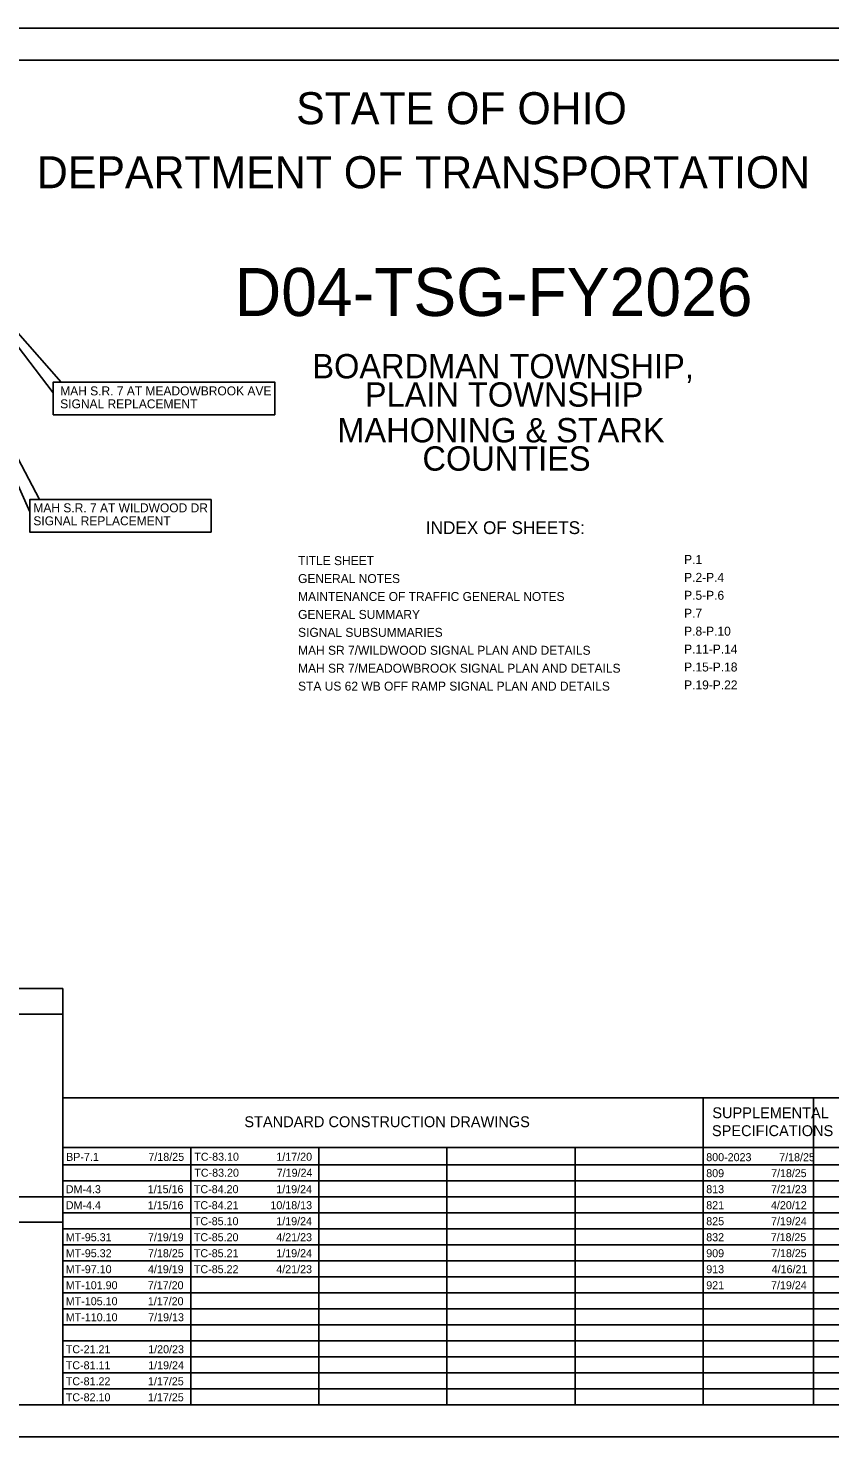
# Model space of a CAD drawing. Extents: x 0 to 29006, y 0 to 889393.
# Drawn here: x 9.61 to 22.13, y 0 to 22 of the extents above; entities that cross this region are included whole.
import ezdxf

# ---------------------------------------------------------------- set-up
doc = ezdxf.new("R2010")
doc.units = 0
for name, color, linetype in [('Default', 7, 'Continuous'), ('SH_Border', 7, 'Continuous'), ('SH_Cut_Line', 7, 'Continuous'), ('SH_Data', 7, 'Continuous'), ('SH_Text', 7, 'Continuous')]:
    doc.layers.add(name, color=color, linetype=linetype)

msp = doc.modelspace()

# ---------------------------------------------------------------- linework, layer by layer
at = {"layer": 'Default'}
for points in [[(10.002, 16.307), (8.244, 18.612), (10.126, 16.474), (10.002, 16.474)], [(9.635, 14.448), (8.269, 17.529), (9.789, 14.637), (9.635, 14.637)], [(10.002, 16.474), (13.461, 16.474), (13.461, 15.962), (10.002, 15.962)], [(9.635, 14.637), (12.467, 14.637), (12.467, 14.131), (9.635, 14.131)]]:
    msp.add_lwpolyline(points, close=True, dxfattribs=at)
at = {"layer": 'SH_Border'}
msp.add_lwpolyline([(1.5, 21.5), (33.5, 21.5), (33.5, 0.5), (1.5, 0.5)], close=True, dxfattribs=at)
at = {"layer": 'SH_Cut_Line'}
msp.add_lwpolyline([(0, 0), (34, 0), (34, 22), (0, 22)], close=True, dxfattribs=at)
at = {"layer": 'SH_Data'}
for p, q in [((7.35, 6.6), (10.15, 6.6)), ((10.15, 5.292), (23.6, 5.292)), ((10.15, 0.5), (10.15, 5.292)), ((20.15, 0.5), (20.15, 5.292)), ((21.875, 0.5), (21.875, 5.292)), ((10.15, 4.521), (23.6, 4.521)), ((12.15, 0.5), (12.15, 4.521)), ((14.15, 0.5), (14.15, 4.521)), ((16.15, 0.5), (16.15, 4.521)), ((18.15, 0.5), (18.15, 4.521)), ((10.15, 4.25), (23.6, 4.25)), ((10.15, 4), (23.6, 4)), ((10.15, 3.75), (23.6, 3.75)), ((7.35, 3.35), (10.15, 3.35)), ((10.15, 3.5), (23.6, 3.5)), ((10.15, 3.25), (23.6, 3.25)), ((10.15, 3), (23.6, 3)), ((10.15, 2.75), (23.6, 2.75)), ((10.15, 2.5), (23.6, 2.5)), ((10.15, 2.25), (23.6, 2.25)), ((10.15, 2), (23.6, 2)), ((10.15, 1.75), (23.6, 1.75)), ((10.15, 1.5), (23.6, 1.5)), ((10.15, 1.25), (23.6, 1.25)), ((10.15, 1), (23.6, 1)), ((10.15, 0.75), (23.6, 0.75))]:
    msp.add_line(p, q, dxfattribs=at)
for points in [[(10.15, 7), (7.35, 7), (7.35, 3.75), (10.15, 3.75)], [(10.15, 3.75), (7.35, 3.75), (7.35, 0.5), (10.15, 0.5)]]:
    msp.add_lwpolyline(points, close=True, dxfattribs=at)

# ---------------------------------------------------------------- texts
at = {"layer": 'Default'}
for s, height, p in [('BP-7.1', 0.125, (10.203, 4.31)), ('7/18/25', 0.125, (11.488, 4.31)), ('TC-83.10', 0.125, (12.205, 4.312)), ('1/17/20', 0.125, (13.486, 4.312)), ('800-2023', 0.125, (20.198, 4.305)), ('7/18/25', 0.125, (21.337, 4.305)), ('TC-83.20', 0.125, (12.205, 4.062)), ('7/19/24', 0.125, (13.492, 4.062)), ('809', 0.125, (20.198, 4.055)), ('7/18/25', 0.1237, (21.213, 4.056)), ('DM-4.3', 0.125, (10.198, 3.805)), ('1/15/16', 0.125, (11.478, 3.805)), ('TC-84.20', 0.125, (12.198, 3.805)), ('1/19/24', 0.125, (13.485, 3.805)), ('813', 0.125, (20.198, 3.805)), ('7/21/23', 0.125, (21.21, 3.805)), ('DM-4.4', 0.125, (10.198, 3.555)), ('1/15/16', 0.125, (11.478, 3.555)), ('TC-84.21', 0.125, (12.198, 3.555)), ('10/18/13', 0.125, (13.393, 3.555)), ('821', 0.125, (20.198, 3.555)), ('4/20/12', 0.125, (21.209, 3.555)), ('TC-85.10', 0.125, (12.198, 3.305)), ('1/19/24', 0.125, (13.485, 3.305)), ('825', 0.125, (20.198, 3.305)), ('7/19/24', 0.125, (21.21, 3.305)), ('MT-95.31', 0.125, (10.198, 3.055)), ('7/19/19', 0.125, (11.481, 3.055)), ('TC-85.20', 0.125, (12.198, 3.055)), ('4/21/23', 0.125, (13.485, 3.055)), ('832', 0.125, (20.198, 3.055)), ('7/18/25', 0.1237, (21.207, 3.056)), ('MT-95.32', 0.125, (10.198, 2.805)), ('7/18/25', 0.125, (11.482, 2.805)), ('TC-85.21', 0.125, (12.198, 2.805)), ('1/19/24', 0.125, (13.485, 2.805)), ('909', 0.125, (20.198, 2.805)), ('7/18/25', 0.1237, (21.213, 2.806)), ('MT-97.10', 0.125, (10.198, 2.555)), ('4/19/19', 0.125, (11.481, 2.555)), ('TC-85.22', 0.125, (12.198, 2.555)), ('4/21/23', 0.125, (13.485, 2.555)), ('913', 0.125, (20.198, 2.555)), ('4/16/21', 0.125, (21.22, 2.555)), ('MT-101.90', 0.125, (10.198, 2.305)), ('7/17/20', 0.125, (11.479, 2.305)), ('921', 0.125, (20.198, 2.305)), ('7/19/24', 0.125, (21.21, 2.305)), ('MT-105.10', 0.125, (10.198, 2.055)), ('1/17/20', 0.125, (11.479, 2.055)), ('MT-110.10', 0.125, (10.198, 1.805)), ('7/19/13', 0.125, (11.485, 1.805)), ('TC-21.21', 0.125, (10.198, 1.305)), ('1/20/23', 0.125, (11.485, 1.305)), ('TC-81.11', 0.125, (10.198, 1.055)), ('1/19/24', 0.125, (11.485, 1.055)), ('TC-81.22', 0.125, (10.198, 0.805)), ('1/17/25', 0.125, (11.482, 0.805)), ('TC-82.10', 0.125, (10.198, 0.555)), ('1/17/25', 0.125, (11.482, 0.555))]:
    msp.add_text(s, height=height, dxfattribs=at).set_placement(p)
at = {"layer": 'SH_Text'}
for s, height, p in [('STATE OF OHIO', 0.5, (13.795, 20.5)), ('DEPARTMENT OF TRANSPORTATION', 0.5, (9.747, 19.5)), ('D04-TSG-FY2026', 0.75, (12.838, 17.505)), ('BOARDMAN TOWNSHIP,', 0.38, (14.048, 16.531)), ('MAH S.R. 7 AT MEADOWBROOK AVE', 0.14, (10.111, 16.265)), ('PLAIN TOWNSHIP', 0.38, (14.868, 16.089)), ('SIGNAL REPLACEMENT', 0.14, (10.111, 16.063)), ('MAHONING & STARK', 0.38, (14.438, 15.531)), ('COUNTIES', 0.38, (15.767, 15.089)), ('MAH S.R. 7 AT WILDWOOD DR', 0.14, (9.692, 14.439)), ('SIGNAL REPLACEMENT', 0.14, (9.692, 14.236)), ('INDEX OF SHEETS:', 0.2, (15.821, 14.099)), ('TITLE SHEET', 0.14, (13.825, 13.614)), ('P.1', 0.14, (19.853, 13.633)), ('GENERAL NOTES', 0.14, (13.825, 13.334)), ('P.2-P.4', 0.14, (19.853, 13.353)), ('P.5-P.6', 0.14, (19.853, 13.073)), ('MAINTENANCE OF TRAFFIC GENERAL NOTES', 0.14, (13.825, 13.054)), ('GENERAL SUMMARY', 0.14, (13.825, 12.774)), ('P.7', 0.14, (19.853, 12.793)), ('SIGNAL SUBSUMMARIES', 0.14, (13.825, 12.494)), ('P.8-P.10', 0.14, (19.853, 12.513)), ('MAH SR 7/WILDWOOD SIGNAL PLAN AND DETAILS', 0.14, (13.825, 12.214)), ('P.11-P.14', 0.14, (19.853, 12.233)), ('MAH SR 7/MEADOWBROOK SIGNAL PLAN AND DETAILS', 0.14, (13.825, 11.934)), ('P.15-P.18', 0.14, (19.853, 11.953)), ('STA US 62 WB OFF RAMP SIGNAL PLAN AND DETAILS', 0.14, (13.825, 11.654)), ('P.19-P.22', 0.14, (19.853, 11.673)), ('SUPPLEMENTAL', 0.17, (20.293, 4.976)), ('STANDARD CONSTRUCTION DRAWINGS', 0.17, (12.986, 4.836)), ('SPECIFICATIONS', 0.17, (20.287, 4.696))]:
    msp.add_text(s, height=height, dxfattribs=at).set_placement(p)

doc.saveas('drawing.dxf')
